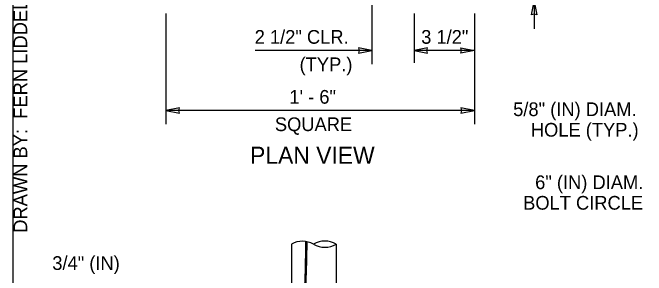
# Model space of a CAD drawing. Extents: x 99862 to 103680, y 99470 to 105076.
# Drawn here: x 99862 to 100603, y 101317 to 101624 of the extents above; entities that cross this region are included whole.
import ezdxf

# ---------------------------------------------------------------- set-up
doc = ezdxf.new("R2010")
doc.units = 0
for name, color, linetype in [('Level 1', 7, 'Continuous'), ('Level 15', 7, 'Continuous'), ('Level 2', 7, 'Continuous'), ('Level 20', 7, 'Continuous'), ('Level 32', 7, 'Continuous'), ('Level 62', 7, 'Continuous')]:
    doc.layers.add(name, color=color, linetype=linetype)

msp = doc.modelspace()

# ---------------------------------------------------------------- linework, layer by layer
at = {"layer": 'Level 1'}
msp.add_lwpolyline([(99862, 99999.5), (103151, 99999.5), (103151, 102075.5), (99862, 102075.5)], close=True, dxfattribs=at)
at = {"layer": 'Level 15'}
for p, q in [((100282.03, 101690.19), (100282.03, 101563.27)), ((100471.83, 101636.77), (100471.83, 101604.77)), ((100041.23, 101622.72), (100041.23, 101493.27)), ((100331.43, 101622.72), (100331.43, 101564.86)), ((100401.83, 101622.72), (100401.83, 101493.27)), ((100282.03, 101579.27), (100145.49, 101579.27)), ((100401.83, 101579.27), (100331.43, 101579.27)), ((100401.83, 101509.27), (100041.23, 101509.27))]:
    msp.add_line(p, q, dxfattribs=at)
for points in [[(100471.83, 101636.77), (100474.91, 101621.04), (100471.83, 101621.77), (100468.74, 101621.04)], [(100282.03, 101579.27), (100266.31, 101582.35), (100267.04, 101579.27), (100266.31, 101576.18)], [(100331.43, 101579.27), (100347.15, 101576.18), (100346.43, 101579.27), (100347.15, 101582.35)], [(100401.83, 101579.27), (100386.1, 101576.18), (100386.83, 101579.27), (100386.1, 101582.35)], [(100041.23, 101509.27), (100056.96, 101506.18), (100056.23, 101509.27), (100056.96, 101512.35)], [(100401.83, 101509.27), (100386.1, 101512.35), (100386.83, 101509.27), (100386.1, 101506.18)]]:
    msp.add_lwpolyline(points, close=True, dxfattribs=at)
at = {"layer": 'Level 2'}
for p, q in [((100188.17, 101353.34), (100188.17, 101177.49)), ((100240.25, 101353.4), (100240.25, 101176.11))]:
    msp.add_line(p, q, dxfattribs=at)
for centre, start, end in [((100200.8, 101330.62), 60, 119.06882), ((100227.25, 101330.89), 60, 121.16768), ((100226.79, 101375.65), 240, 301.1679)]:
    msp.add_arc(centre, 26, start, end, dxfattribs=at)
at = {"layer": 'Level 32'}
for points, degree in [([(100211.4, 101167.48), (100196.47, 101215.92), (100204.73, 101302.58), (100204.72, 101356.33)], 2), ([(100213.01, 101167.43), (100208.53, 101182.06), (100206.17, 101199.28), (100203.81, 101236.82), (100203.81, 101257.16), (100204.64, 101297.3), (100205.47, 101317.11), (100206.11, 101342.33), (100206.24, 101349.43), (100206.24, 101356.04)], 3)]:
    msp.add_open_spline(points, degree=degree, dxfattribs=at)

# ---------------------------------------------------------------- texts
at = {"layer": 'Level 20'}
for s, height, p in [('2 1/2" CLR.', 16, (100144.96, 101587.27)), ('(TYP.)', 16, (100197.48, 101555.27)), ('1\' - 6"', 16, (100185.54, 101517.27)), ('SQUARE', 16, (100168.59, 101485.27)), ('PLAN VIEW', 20, (100139.61, 101447.06)), ('3/4" (IN)', 16, (99908.3, 101323.15))]:
    msp.add_text(s, height=height, dxfattribs=at).set_placement(p)
for s, p in [('3 1/2"', (100339.66, 101587.27)), ('5/8" (IN) DIAM.', (100447.22, 101502.81)), ('HOLE (TYP.)', (100467.89, 101478.81)), ('6" (IN) DIAM.', (100472.92, 101417.52)), ('BOLT CIRCLE', (100458.86, 101393.52))]:
    msp.add_text(s, height=16, rotation=360, dxfattribs=at).set_placement(p)
at = {"layer": 'Level 62'}
msp.add_text('DRAWN BY:  FERN LIDDELL', height=16, rotation=90, dxfattribs=at).set_placement((99879, 101366.54))

doc.saveas('drawing.dxf')
